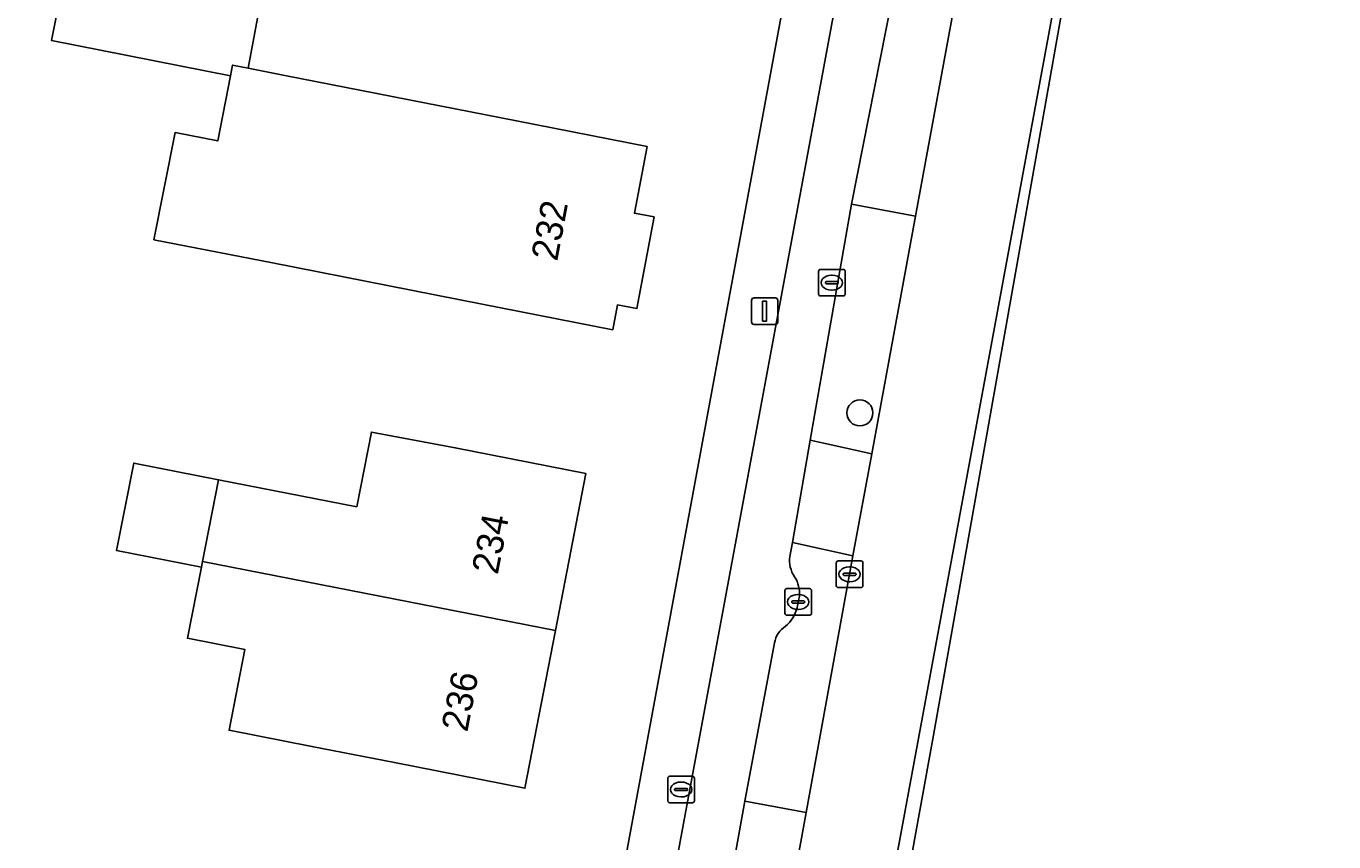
# Model space of a CAD drawing. Extents: x 161258 to 161838, y 380833 to 381727.
# Drawn here: x 161737.48 to 161786.62, y 381273.67 to 381304.33 of the extents above; entities that cross this region are included whole.
import ezdxf

# ---------------------------------------------------------------- set-up
doc = ezdxf.new("R2010")
doc.units = 0
for name, color, linetype in [('IMGEO_Berm_groen', 7, 'Continuous'), ('IMGEO_Boom', 7, 'Continuous'), ('IMGEO_Brandkraan', 7, 'Continuous'), ('IMGEO_Erf', 7, 'Continuous'), ('IMGEO_Fietspad_open', 7, 'Continuous'), ('IMGEO_Kolk', 7, 'Continuous'), ('IMGEO_Lichtmast', 7, 'Continuous'), ('IMGEO_OVBaan_gesloten', 7, 'Continuous'), ('IMGEO_Pand', 7, 'Continuous'), ('IMGEO_Pand_nummerreeks', 7, 'Continuous'), ('IMGEO_Rijbaan_lokaal_open', 7, 'Continuous'), ('IMGEO_Rijbaan_regionaal_gesloten', 7, 'Continuous'), ('IMGEO_Rioolput', 7, 'Continuous'), ('IMGEO_Voetpad_open', 7, 'Continuous')]:
    doc.layers.add(name, color=color, linetype=linetype)

msp = doc.modelspace()

# ---------------------------------------------------------------- linework, layer by layer
at = {"layer": 'IMGEO_Berm_groen'}
msp.add_lwpolyline([(161770.901, 381297.185), (161768.496, 381297.63), (161766.944, 381288.761), (161769.258, 381288.25)], close=True, dxfattribs=at)
for points in [[(161768.425, 381283.725), (161768.553, 381284.422), (161766.274, 381284.919), (161766.182, 381284.389)], [(161765.608, 381281.141), (161764.484, 381275.198), (161766.79, 381274.775), (161768.425, 381283.725)], [(161766.539, 381282.888), (161766.49, 381282.685), (161766.45, 381282.462)]]:
    msp.add_lwpolyline(points, dxfattribs=at)
for centre, radius, start, end in [((161767.209, 381284.228), 1.039, 171.0694, 214.964), ((161765.362, 381282.994), 1.182, 354.8328, 32.6591), ((161765.182, 381282.778), 1.307, 309.6557, 346.0057), ((161766.479, 381281.025), 0.879, 121.8128, 172.4144)]:
    msp.add_arc(centre, radius, start, end, dxfattribs=at)
at = {"layer": 'IMGEO_Boom'}
msp.add_circle((161768.813, 381289.789), 0.489, dxfattribs=at)
at = {"layer": 'IMGEO_Brandkraan'}
for p, q in [((161761.591, 381275.209), (161761.591, 381276.061)), ((161761.666, 381276.135), (161762.518, 381276.135)), ((161761.893, 381275.678), (161762.291, 381275.678)), ((161762.079, 381275.915), (161762.104, 381275.915)), ((161762.592, 381276.061), (161762.592, 381275.209)), ((161761.85, 381275.629), (161761.85, 381275.641)), ((161762.288, 381275.592), (161761.89, 381275.592)), ((161762.102, 381275.355), (161762.077, 381275.355)), ((161762.334, 381275.641), (161762.334, 381275.629)), ((161762.518, 381275.135), (161761.666, 381275.135))]:
    msp.add_line(p, q, dxfattribs=at)
for points in [[(161761.591, 381275.209), (161761.591, 381276.061)], [(161761.666, 381276.135), (161762.518, 381276.135)], [(161762.592, 381276.061), (161762.592, 381275.209)], [(161762.518, 381275.135), (161761.666, 381275.135)]]:
    msp.add_lwpolyline(points, dxfattribs=at)
for centre, radius, start, end in [((161761.668, 381276.059), 0.0765, 91.552, 178.448), ((161761.668, 381276.059), 0.0765, 91.552, 178.448), ((161761.89, 381275.638), 0.0403, 85.8775, 175.7526), ((161762.295, 381275.64), 0.0386, 1.7309, 96.639), ((161762.516, 381276.059), 0.0765, 1.552, 88.448), ((161762.516, 381276.059), 0.0765, 1.552, 88.448), ((161761.668, 381275.211), 0.0765, 181.552, 268.448), ((161761.668, 381275.211), 0.0765, 181.552, 268.448), ((161761.887, 381275.628), 0.0366, 178.938, 274.7102), ((161762.291, 381275.635), 0.043, 264.8664, 352.4533), ((161762.516, 381275.211), 0.0765, 271.552, 358.448), ((161762.516, 381275.211), 0.0765, 271.552, 358.448)]:
    msp.add_arc(centre, radius, start, end, dxfattribs=at)
for centre, major_axis, ratio, start_param, end_param in [((161762.078, 381275.635), (-0.387, 0.002), 0.722429, 4.712389, 7.853982), ((161762.103, 381275.635), (-0.39, 0.002), 0.717154, 1.570796, 4.712389)]:
    msp.add_ellipse(centre, major_axis=major_axis, ratio=ratio, start_param=start_param, end_param=end_param, dxfattribs=at)
at = {"layer": 'IMGEO_Erf'}
msp.add_lwpolyline([(161668.77, 381167.385), (161673.77, 381165.793), (161737.053, 381153.773), (161737.441, 381153.699), (161737.997, 381153.598), (161738.112, 381154.157), (161737.938, 381154.198), (161753.579, 381238.309), (161753.673, 381238.82), (161753.349, 381239.081), (161753.133, 381238.804), (161751.742, 381240.033), (161751.586, 381239.216), (161750.481, 381239.459), (161750.713, 381240.543), (161751.212, 381243.492), (161751.454, 381244.596), (161752.571, 381244.423), (161752.507, 381243.755), (161754.157, 381244.071), (161754.273, 381243.898), (161754.635, 381244.025), (161769.385, 381323.827)], dxfattribs=at)
for points in [[(161746.736, 381295.425), (161742.281, 381296.299), (161743.072, 381300.327), (161744.676, 381300.012), (161745.156, 381302.458), (161738.434, 381303.783), (161739.069, 381307.013), (161737.099, 381307.382), (161738.382, 381316.587), (161741.592, 381315.986), (161740.78, 381310.162), (161746.989, 381309), (161746.362, 381305.647), (161745.82, 381302.749), (161747.205, 381302.476), (161755.905, 381300.762), (161760.811, 381299.8), (161760.341, 381297.293), (161761.078, 381297.154), (161760.433, 381293.711), (161759.696, 381293.85), (161759.522, 381292.917), (161754.616, 381293.879)], [(161740.874, 381284.614), (161741.519, 381287.902), (161744.707, 381287.278), (161749.901, 381286.261), (161750.453, 381289.07), (161753.602, 381288.478), (161758.508, 381287.517), (161757.367, 381281.611), (161756.222, 381275.684), (161751.316, 381276.644), (161748.215, 381277.251), (161745.103, 381277.86), (161745.697, 381280.896), (161743.54, 381281.318), (161744.063, 381283.99)]]:
    msp.add_lwpolyline(points, close=True, dxfattribs=at)
at = {"layer": 'IMGEO_Fietspad_open'}
for points in [[(161766.182, 381284.389), (161766.274, 381284.919), (161766.944, 381288.761), (161768.496, 381297.63), (161770.018, 381305.316), (161770.601, 381308.32), (161771.852, 381315.075), (161772.289, 381317.394), (161770.217, 381317.745), (161769.724, 381315.032), (161762.12, 381274.018), (161757.67, 381250), (161756.52, 381243.79), (161755.513, 381238.354), (161742.385, 381167.493), (161739.245, 381150.478), (161741.31, 381150.032), (161742.611, 381157.056), (161742.773, 381157.406), (161743.019, 381157.715)], [(161766.45, 381282.462), (161766.49, 381282.685), (161766.539, 381282.888)], [(161761.832, 381260.889), (161763.128, 381267.9), (161763.646, 381270.534), (161764.484, 381275.198), (161765.608, 381281.141)]]:
    msp.add_lwpolyline(points, dxfattribs=at)
for centre, radius, start, end in [((161767.209, 381284.228), 1.039, 171.0694, 214.964), ((161765.362, 381282.994), 1.182, 354.8328, 32.6591), ((161765.182, 381282.778), 1.307, 309.6557, 346.0057), ((161766.479, 381281.025), 0.879, 121.8128, 172.4144)]:
    msp.add_arc(centre, radius, start, end, dxfattribs=at)
at = {"layer": 'IMGEO_Kolk'}
for p, q in [((161767.926, 381283.299), (161767.926, 381284.151)), ((161768.001, 381284.225), (161768.853, 381284.225)), ((161768.927, 381284.151), (161768.927, 381283.299)), ((161768.185, 381283.719), (161768.185, 381283.731)), ((161768.623, 381283.682), (161768.225, 381283.682)), ((161768.228, 381283.768), (161768.626, 381283.768)), ((161768.414, 381284.005), (161768.439, 381284.005)), ((161768.669, 381283.731), (161768.669, 381283.719)), ((161765.994, 381282.259), (161765.994, 381283.111)), ((161766.069, 381283.185), (161766.921, 381283.185)), ((161766.995, 381283.111), (161766.995, 381282.259)), ((161768.853, 381283.225), (161768.001, 381283.225)), ((161768.437, 381283.445), (161768.412, 381283.445)), ((161766.253, 381282.679), (161766.253, 381282.691)), ((161766.691, 381282.642), (161766.293, 381282.642)), ((161766.296, 381282.728), (161766.694, 381282.728)), ((161766.482, 381282.965), (161766.507, 381282.965)), ((161766.737, 381282.691), (161766.737, 381282.679)), ((161766.921, 381282.185), (161766.069, 381282.185)), ((161766.505, 381282.405), (161766.48, 381282.405))]:
    msp.add_line(p, q, dxfattribs=at)
for points in [[(161767.926, 381283.299), (161767.926, 381284.151)], [(161768.001, 381284.225), (161768.853, 381284.225)], [(161768.927, 381284.151), (161768.927, 381283.299)], [(161765.994, 381282.259), (161765.994, 381283.111)], [(161766.069, 381283.185), (161766.921, 381283.185)], [(161766.995, 381283.111), (161766.995, 381282.259)], [(161768.853, 381283.225), (161768.001, 381283.225)], [(161766.921, 381282.185), (161766.069, 381282.185)]]:
    msp.add_lwpolyline(points, dxfattribs=at)
for centre, radius, start, end in [((161768.003, 381284.149), 0.0765, 91.552, 178.448), ((161768.003, 381284.149), 0.0765, 91.552, 178.448), ((161768.851, 381284.149), 0.0765, 1.552, 88.448), ((161768.851, 381284.149), 0.0765, 1.552, 88.448), ((161768.225, 381283.728), 0.0403, 85.8775, 175.7526), ((161768.222, 381283.718), 0.0366, 178.938, 274.7102), ((161768.626, 381283.725), 0.043, 264.8664, 352.4533), ((161768.63, 381283.73), 0.0386, 1.7309, 96.639), ((161766.071, 381283.109), 0.0765, 91.552, 178.448), ((161766.071, 381283.109), 0.0765, 91.552, 178.448), ((161766.919, 381283.109), 0.0765, 1.552, 88.448), ((161766.919, 381283.109), 0.0765, 1.552, 88.448), ((161768.003, 381283.301), 0.0765, 181.552, 268.448), ((161768.003, 381283.301), 0.0765, 181.552, 268.448), ((161768.851, 381283.301), 0.0765, 271.552, 358.448), ((161768.851, 381283.301), 0.0765, 271.552, 358.448), ((161766.293, 381282.688), 0.0403, 85.8775, 175.7526), ((161766.29, 381282.678), 0.0366, 178.938, 274.7102), ((161766.694, 381282.685), 0.043, 264.8664, 352.4533), ((161766.698, 381282.69), 0.0386, 1.7309, 96.639), ((161766.071, 381282.261), 0.0765, 181.552, 268.448), ((161766.071, 381282.261), 0.0765, 181.552, 268.448), ((161766.919, 381282.261), 0.0765, 271.552, 358.448), ((161766.919, 381282.261), 0.0765, 271.552, 358.448)]:
    msp.add_arc(centre, radius, start, end, dxfattribs=at)
for centre, major_axis, ratio, start_param, end_param in [((161768.413, 381283.725), (-0.387, 0.002), 0.722429, 4.712389, 7.853982), ((161768.438, 381283.725), (-0.39, 0.002), 0.717154, 1.570796, 4.712389), ((161766.481, 381282.685), (-0.387, 0.002), 0.722429, 4.712389, 7.853982), ((161766.506, 381282.685), (-0.39, 0.002), 0.717154, 1.570796, 4.712389)]:
    msp.add_ellipse(centre, major_axis=major_axis, ratio=ratio, start_param=start_param, end_param=end_param, dxfattribs=at)
at = {"layer": 'IMGEO_Lichtmast'}
for p, q in [((161764.737, 381293.214), (161764.737, 381294.014)), ((161764.737, 381294.014), (161764.737, 381293.214)), ((161764.837, 381294.114), (161765.627, 381294.114)), ((161765.627, 381294.114), (161764.837, 381294.114)), ((161765.727, 381294.014), (161765.727, 381293.214)), ((161765.727, 381293.214), (161765.727, 381294.014)), ((161765.627, 381293.114), (161764.837, 381293.114)), ((161764.837, 381293.114), (161765.627, 381293.114))]:
    msp.add_line(p, q, dxfattribs=at)
msp.add_lwpolyline([(161765.157, 381293.989), (161765.307, 381293.989), (161765.307, 381293.239), (161765.157, 381293.239), (161765.157, 381293.989)], dxfattribs=at)
for centre, start, end in [((161764.837, 381294.014), 90, 180), ((161764.837, 381294.014), 90, 180), ((161765.627, 381294.014), 0, 90), ((161765.627, 381294.014), 360, 90), ((161764.837, 381293.214), 180, 270), ((161764.837, 381293.214), 180, 270), ((161765.627, 381293.214), 270, 0), ((161765.627, 381293.214), 270, 0)]:
    msp.add_arc(centre, 0.1, start, end, dxfattribs=at)
at = {"layer": 'IMGEO_OVBaan_gesloten'}
msp.add_lwpolyline([(161733.581, 381071.116), (161732.705, 381071.238), (161742.349, 381122.541), (161776.386, 381306.634), (161776.704, 381306.578), (161771.577, 381277.677), (161758.366, 381204.804), (161740.263, 381107.16), (161733.581, 381071.116)], dxfattribs=at)
at = {"layer": 'IMGEO_Pand'}
for points in [[(161746.362, 381305.647), (161741.466, 381306.564), (161739.069, 381307.013), (161738.434, 381303.783), (161745.156, 381302.458), (161745.236, 381302.864), (161745.82, 381302.749)], [(161760.811, 381299.8), (161755.905, 381300.762), (161747.205, 381302.476), (161745.82, 381302.749), (161745.236, 381302.864), (161745.156, 381302.458), (161744.676, 381300.012), (161743.072, 381300.327), (161742.281, 381296.299), (161746.736, 381295.425), (161754.616, 381293.879), (161759.522, 381292.917), (161759.696, 381293.85), (161760.433, 381293.711), (161761.078, 381297.154), (161760.341, 381297.293)], [(161744.105, 381284.205), (161757.367, 381281.611), (161758.508, 381287.517), (161753.602, 381288.478), (161750.453, 381289.07), (161749.901, 381286.261), (161744.707, 381287.278)], [(161744.707, 381287.278), (161741.519, 381287.902), (161740.874, 381284.614), (161744.063, 381283.99), (161744.105, 381284.205)], [(161757.367, 381281.611), (161744.105, 381284.205), (161744.063, 381283.99), (161743.54, 381281.318), (161745.697, 381280.896), (161745.103, 381277.86), (161748.215, 381277.251), (161751.316, 381276.644), (161756.222, 381275.684)]]:
    msp.add_lwpolyline(points, close=True, dxfattribs=at)
at = {"layer": 'IMGEO_Rijbaan_lokaal_open'}
for points in [[(161772.327, 381304.942), (161770.018, 381305.316), (161768.496, 381297.63), (161770.901, 381297.185)], [(161769.258, 381288.25), (161766.944, 381288.761), (161766.274, 381284.919), (161768.553, 381284.422)], [(161766.79, 381274.775), (161764.484, 381275.198), (161763.646, 381270.534), (161765.936, 381270.097)]]:
    msp.add_lwpolyline(points, close=True, dxfattribs=at)
at = {"layer": 'IMGEO_Rijbaan_regionaal_gesloten'}
for points in [[(161732.705, 381071.484), (161732.705, 381071.238), (161742.349, 381122.541), (161776.386, 381306.634), (161779.513, 381323.547), (161779.709, 381323.516), (161781.032, 381330.976), (161790.829, 381386.201), (161813.475, 381504.752), (161831.216, 381599.902), (161831.886, 381604.233), (161835.772, 381629.362), (161830.258, 381630.974)], [(161775.225, 381320.76), (161775.137, 381320.241), (161774.55, 381317.025), (161773.958, 381313.603), (161772.327, 381304.942), (161770.901, 381297.185), (161769.258, 381288.25), (161768.553, 381284.422), (161768.425, 381283.725), (161766.79, 381274.775), (161765.936, 381270.097), (161765.448, 381267.467), (161764.164, 381260.618), (161762.229, 381250), (161761.225, 381244.487), (161759.812, 381236.731), (161759.764, 381236.501), (161756.087, 381216.391)]]:
    msp.add_lwpolyline(points, dxfattribs=at)
at = {"layer": 'IMGEO_Rioolput'}
for p, q in [((161767.258, 381294.258), (161767.258, 381295.11)), ((161767.333, 381295.184), (161768.185, 381295.184)), ((161767.746, 381294.964), (161767.771, 381294.964)), ((161768.259, 381295.11), (161768.259, 381294.258)), ((161767.517, 381294.678), (161767.517, 381294.69)), ((161767.955, 381294.641), (161767.557, 381294.641)), ((161767.56, 381294.727), (161767.958, 381294.727)), ((161767.769, 381294.404), (161767.744, 381294.404)), ((161768.001, 381294.69), (161768.001, 381294.678)), ((161768.185, 381294.184), (161767.333, 381294.184))]:
    msp.add_line(p, q, dxfattribs=at)
for points in [[(161767.258, 381294.258), (161767.258, 381295.11)], [(161767.333, 381295.184), (161768.185, 381295.184)], [(161768.259, 381295.11), (161768.259, 381294.258)], [(161768.185, 381294.184), (161767.333, 381294.184)]]:
    msp.add_lwpolyline(points, dxfattribs=at)
for centre, radius, start, end in [((161767.335, 381295.108), 0.0765, 91.552, 178.448), ((161767.335, 381295.108), 0.0765, 91.552, 178.448), ((161768.183, 381295.108), 0.0765, 1.552, 88.448), ((161768.183, 381295.108), 0.0765, 1.552, 88.448), ((161767.557, 381294.687), 0.0403, 85.8775, 175.7526), ((161767.554, 381294.677), 0.0366, 178.938, 274.7102), ((161767.958, 381294.684), 0.043, 264.8664, 352.4533), ((161767.962, 381294.689), 0.0386, 1.7309, 96.639), ((161767.335, 381294.26), 0.0765, 181.552, 268.448), ((161767.335, 381294.26), 0.0765, 181.552, 268.448), ((161768.183, 381294.26), 0.0765, 271.552, 358.448), ((161768.183, 381294.26), 0.0765, 271.552, 358.448)]:
    msp.add_arc(centre, radius, start, end, dxfattribs=at)
for centre, major_axis, ratio, start_param, end_param in [((161767.745, 381294.684), (-0.387, 0.002), 0.722429, 4.712389, 7.853982), ((161767.77, 381294.684), (-0.39, 0.002), 0.717154, 1.570796, 4.712389)]:
    msp.add_ellipse(centre, major_axis=major_axis, ratio=ratio, start_param=start_param, end_param=end_param, dxfattribs=at)
at = {"layer": 'IMGEO_Voetpad_open'}
for points in [[(161770.217, 381317.745), (161771.375, 381324.109), (161769.385, 381323.827), (161754.635, 381244.025), (161753.673, 381238.82), (161753.579, 381238.309), (161737.938, 381154.198), (161738.112, 381154.157), (161737.997, 381153.598), (161737.441, 381153.699), (161737.053, 381153.773), (161736.521, 381150.931), (161736.147, 381148.935), (161736.914, 381148.802)], [(161739.245, 381150.478), (161742.385, 381167.493), (161755.513, 381238.354), (161756.52, 381243.79), (161757.67, 381250), (161762.12, 381274.018), (161769.724, 381315.032), (161770.217, 381317.745)]]:
    msp.add_lwpolyline(points, dxfattribs=at)

# ---------------------------------------------------------------- texts
at = {"layer": 'IMGEO_Pand_nummerreeks'}
for s, rotation, p in [('232', 79.3948, (161757.435, 381295.464)), ('234', 79.0658, (161755.2, 381283.684)), ('236', 79.0682, (161754.057, 381277.766))]:
    msp.add_text(s, height=1, rotation=rotation, dxfattribs=at).set_placement(p)

doc.saveas('drawing.dxf')
